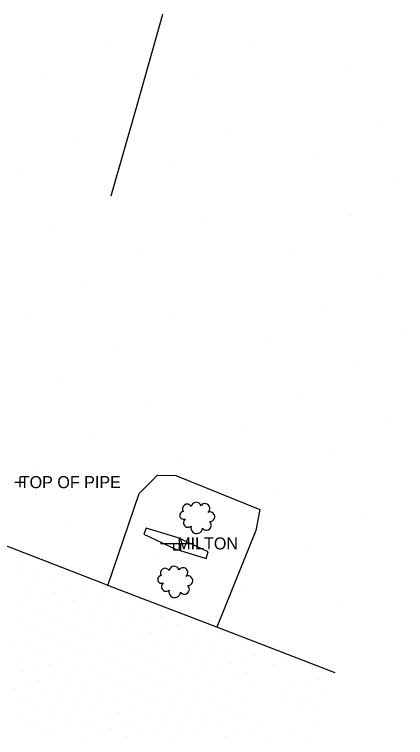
# Model space of a CAD drawing. Extents: x 1733582 to 1734070, y 467256 to 468256.
# Drawn here: x 1733982.2 to 1734040.7, y 468019.3 to 468127.5 of the extents above; entities that cross this region are included whole.
import ezdxf

# ---------------------------------------------------------------- set-up
doc = ezdxf.new("R2010")
doc.units = 0
for name, color, linetype in [('Default', 7, 'Continuous'), ('S_Drainage_Invert_Culvert', 7, 'Continuous'), ('S_Ground_LevelString', 7, 'Continuous'), ('S_Ground_SpotElevation', 7, 'Continuous'), ('S_Misc_MiscFeature', 7, 'Continuous'), ('S_Property_Garden', 7, 'Continuous'), ('S_Roadway_Drive_Paved', 7, 'Continuous'), ('S_Text', 7, 'Continuous'), ('S_Traffic_Sign_SinglePost', 7, 'Continuous'), ('S_Trees_Bush', 7, 'Continuous')]:
    doc.layers.add(name, color=color, linetype=linetype)

# ---------------------------------------------------------------- blocks, each defined once
blk = doc.blocks.new('POINT_DISPLAY')
at = {"layer": 'Default'}
blk.add_line((0, 0), (0, 0), dxfattribs=at)

msp = doc.modelspace()

# ---------------------------------------------------------------- linework, layer by layer
at = {"layer": 'S_Drainage_Invert_Culvert'}
for p, q in [((1733982.96, 468058.27), (1733982.96, 468056.77)), ((1733982.21, 468057.52), (1733983.71, 468057.52))]:
    msp.add_line(p, q, dxfattribs=at)
at = {"layer": 'S_Ground_LevelString'}
msp.add_lwpolyline([(1734004.33, 468127.49), (1734000.46, 468113.89), (1733996.59, 468100.29)], dxfattribs=at)
at = {"layer": 'S_Misc_MiscFeature'}
msp.add_lwpolyline([(1734011.16, 468047.07), (1734006.67, 468049.19), (1734001.88, 468050.61), (1734001.51, 468049.72), (1734006.15, 468047.52), (1734010.82, 468046.08), (1734011.16, 468047.07)], dxfattribs=at)
at = {"layer": 'S_Property_Garden'}
msp.add_lwpolyline([(1733996.14, 468042.05), (1734000.82, 468055.84), (1734003.55, 468058.55), (1734006.31, 468058.5), (1734018.85, 468053.42), (1734018.29, 468050.27), (1734012.45, 468035.8)], dxfattribs=at)
at = {"layer": 'S_Roadway_Drive_Paved'}
msp.add_lwpolyline([(1734030.16, 468029.01), (1734012.45, 468035.8), (1733996.14, 468042.05), (1733995.67, 468042.23), (1733969.92, 468052.24), (1733965.51, 468055.16), (1733962.16, 468059.58), (1733958.83, 468065.66)], dxfattribs=at)
at = {"layer": 'S_Traffic_Sign_SinglePost'}
msp.add_line((1734004.01, 468048.35), (1734009.01, 468048.35), dxfattribs=at)
msp.add_lwpolyline([(1734006.01, 468048.35), (1734007.01, 468048.35), (1734007.01, 468047.35), (1734006.01, 468047.35)], close=True, dxfattribs=at)
at = {"layer": 'S_Trees_Bush'}
for centre, radius, start, end in [((1734008, 468053.5), 0.716, 33.6405, 213.5909), ((1734009.35, 468053.73), 0.774, 19.7277, 168.0032), ((1734010.67, 468053.59), 0.714, 304.7168, 145.2832), ((1734007.46, 468052.53), 0.575, 95.1875, 295.4615), ((1734011.4, 468052.34), 0.731, 268.122, 116.0172), ((1734008.15, 468051.46), 0.705, 129.1555, 309.4105), ((1734010.87, 468051.07), 0.74, 216.9809, 47.4965), ((1734009.42, 468050.68), 0.861, 163.7427, 356.276), ((1734004.72, 468043.92), 0.716, 33.6405, 213.5909), ((1734006.07, 468044.16), 0.774, 19.7277, 168.0032), ((1734007.39, 468044.01), 0.714, 304.7168, 145.2832), ((1734004.17, 468042.95), 0.575, 95.1875, 295.4615), ((1734008.11, 468042.77), 0.731, 268.122, 116.0172), ((1734004.87, 468041.89), 0.705, 129.1555, 309.4105), ((1734007.59, 468041.49), 0.74, 216.9809, 47.4965), ((1734006.14, 468041.1), 0.861, 163.7427, 356.276)]:
    msp.add_arc(centre, radius, start, end, dxfattribs=at)

# ---------------------------------------------------------------- block references
at = {"layer": 'S_Ground_SpotElevation'}
for p in [(1734004.33, 468127.49), (1734017.93, 468123.62), (1733995.59, 468122.63), (1734031.53, 468119.75), (1734009.19, 468118.75), (1733986.86, 468117.76), (1734000.46, 468113.89), (1734036.4, 468111.01), (1734014.06, 468110.02), (1733991.72, 468109.02), (1734027.66, 468106.15), (1734005.32, 468105.15), (1733982.98, 468104.16), (1734039.31, 468102.62), (1733996.59, 468100.29), (1734032.53, 468097.41), (1734010.19, 468096.42), (1733987.85, 468095.42), (1734001.45, 468091.55), (1734023.79, 468092.54), (1734037.39, 468088.67), (1733992.71, 468086.69), (1734028.65, 468083.81), (1733983.98, 468081.82), (1734006.32, 468082.81), (1734040.67, 468079.98), (1734019.92, 468078.94), (1733997.58, 468077.95), (1734033.52, 468075.07), (1733988.84, 468073.08), (1734024.78, 468070.21), (1734002.44, 468069.21), (1734037.8, 468066.28), (1734016.05, 468065.34), (1733993.71, 468064.35), (1734029.65, 468061.47), (1734007.31, 468060.48), (1733984.97, 468059.48), (1734020.91, 468056.6), (1734034.51, 468052.73), (1734012.17, 468051.74), (1733989.83, 468050.75), (1734025.78, 468047.87), (1734003.44, 468046.87), (1733982.64, 468045.59), (1733985.18, 468044.25), (1733983.26, 468043.61), (1733987.6, 468043.01), (1733989.36, 468043.57), (1733983.9, 468041.88), (1733985.69, 468042.42), (1733990.17, 468041.83), (1733992.12, 468042.16), (1733986.32, 468040.67), (1733988.27, 468041.04), (1733994.5, 468040.89), (1734017.05, 468041.55), (1733984.45, 468039.94), (1733990.79, 468039.74), (1733992.53, 468040.47), (1733997.14, 468039.72), (1733982.47, 468039.37), (1733987.01, 468038.51), (1733988.73, 468039.28), (1733995.23, 468039.01), (1734001.37, 468038.89), (1734030.64, 468039.13), (1733983.08, 468037.42), (1733985.09, 468038.06), (1733991.42, 468037.81), (1733993.29, 468038.41), (1733997.51, 468037.54), (1733999.51, 468038.32), (1733987.5, 468036.82), (1733989.39, 468037.1), (1733993.81, 468036.68), (1733995.74, 468037.14), (1734000.21, 468036.47), (1734002.11, 468037.09), (1734003.96, 468037.4), (1733983.6, 468035.48), (1733985.64, 468036), (1733989.97, 468035.42), (1733991.93, 468035.97), (1733996.23, 468035.39), (1733998.21, 468035.85), (1734004.51, 468035.82), (1734006.4, 468036.19), (1734010.71, 468035.31), (1733986.08, 468034.3), (1733988.01, 468034.83), (1733994.21, 468034.75), (1734000.83, 468034.45), (1734002.66, 468035.07), (1734007.06, 468034.2), (1734009.04, 468034.93), (1734013.42, 468034.18), (1733982.38, 468033.13), (1733984.17, 468033.49), (1733990.49, 468033.54), (1733992.58, 468034.02), (1733997.01, 468033.21), (1733998.83, 468033.77), (1734005.25, 468033.72), (1734011.3, 468033.62), (1733986.75, 468032.17), (1733988.61, 468032.94), (1733993.04, 468032.27), (1733995.01, 468032.62), (1733999.36, 468032.01), (1734001.13, 468032.68), (1734003.33, 468033.05), (1734007.69, 468032.49), (1734009.53, 468033), (1734014.02, 468032.21), (1734015.94, 468032.89), (1733982.86, 468030.94), (1733984.95, 468031.68), (1733991.12, 468031.62), (1733997.53, 468031.36), (1734003.92, 468031.19), (1734005.68, 468031.98), (1734011.89, 468031.63), (1734018.23, 468031.53), (1733987.3, 468030.2), (1733989.26, 468030.88), (1733993.58, 468030.14), (1733995.7, 468030.82), (1733999.87, 468030.12), (1734001.95, 468030.61), (1734006.31, 468029.99), (1734008.14, 468030.68), (1734010.11, 468030.9), (1734014.59, 468030.39), (1734016.49, 468030.78), (1734020.83, 468030.2), (1734022.76, 468030.73), (1733983.44, 468029.12), (1733985.32, 468029.79), (1733989.86, 468028.91), (1733991.83, 468029.63), (1733996.19, 468029.04), (1733998, 468029.58), (1734002.54, 468028.78), (1734004.35, 468029.21), (1734010.67, 468029.18), (1734012.71, 468029.75), (1734017.06, 468029.02), (1733985.96, 468027.87), (1733987.89, 468028.6), (1733994.36, 468028.32), (1734000.52, 468028.12), (1734006.85, 468027.95), (1734008.82, 468028.66), (1734015.03, 468028.32), (1734027.78, 468027.97), (1733983.95, 468027.2), (1733988.59, 468026.61), (1733990.39, 468027.19), (1733992.32, 468027.59), (1733996.87, 468027.01), (1733998.56, 468027.49), (1734003.16, 468026.72), (1734005.08, 468027.42), (1734009.43, 468026.63), (1734011.33, 468027.24), (1734017.65, 468026.94), (1734023.86, 468027.03), (1734025.87, 468027.59), (1733982.27, 468026.58), (1733986.66, 468025.95), (1733992.95, 468025.7), (1733994.85, 468026.28), (1733999.27, 468025.69), (1734001.17, 468026.13), (1734007.32, 468026.18), (1734013.65, 468026.02), (1734021.99, 468026.54), (1734028.35, 468026.38), (1733982.8, 468024.64), (1733984.69, 468025.2), (1733989.14, 468024.55), (1733990.96, 468025.16), (1733995.35, 468024.47), (1733997.29, 468024.85), (1734001.73, 468024.45), (1734003.61, 468024.72), (1734005.67, 468025.38), (1734009.78, 468024.74), (1734011.86, 468025.39), (1734016.37, 468024.48), (1734022.7, 468024.55), (1734024.39, 468024.86), (1734026.41, 468025.42), (1733987.31, 468024.09), (1733993.54, 468023.92), (1733999.8, 468023.59), (1734005.92, 468023.53), (1734008.13, 468024.3), (1734012.52, 468023.42), (1734014.31, 468024.19), (1734027, 468023.54), (1733983.35, 468022.72), (1733985.15, 468023.28), (1733989.64, 468022.6), (1733991.42, 468023.21), (1733996.04, 468022.54), (1733997.86, 468022.99), (1734002.28, 468022.38), (1734004.19, 468023.03), (1734010.37, 468022.86), (1734016.73, 468022.81), (1734025.02, 468023.21), (1733985.8, 468021.62), (1733987.75, 468021.94), (1733992.1, 468021.23), (1733993.91, 468021.91), (1734000.28, 468021.76), (1734006.86, 468021.6), (1734008.57, 468022.22), (1734012.86, 468021.59), (1734015.09, 468022.11), (1734019.37, 468021.19), (1734027.71, 468021.91), (1733983.81, 468020.9), (1733988.37, 468020.27), (1733990.23, 468020.76), (1733996.69, 468020.68), (1733998.38, 468021.16), (1734002.75, 468020.57), (1734004.71, 468020.97), (1734009.05, 468020.34), (1734011, 468020.98), (1734015.66, 468020.13), (1734017.41, 468020.59), (1734023.87, 468020.56), (1733986.52, 468019.7), (1733992.87, 468019.4), (1733994.57, 468019.94), (1733999.07, 468019.44), (1734000.96, 468020.09), (1734005.27, 468019.31), (1734007.23, 468019.93), (1734013.6, 468019.51), (1734019.82, 468019.4), (1734026.07, 468019.41)]:
    msp.add_blockref('POINT_DISPLAY', p, dxfattribs=at)

# ---------------------------------------------------------------- texts
at = {"layer": 'S_Text'}
for s, p in [('TOP OF PIPE', (1733982.96, 468056.62)), ('MILTON', (1734006.51, 468047.45))]:
    msp.add_text(s, height=1.8, dxfattribs=at).set_placement(p)

doc.saveas('drawing.dxf')
